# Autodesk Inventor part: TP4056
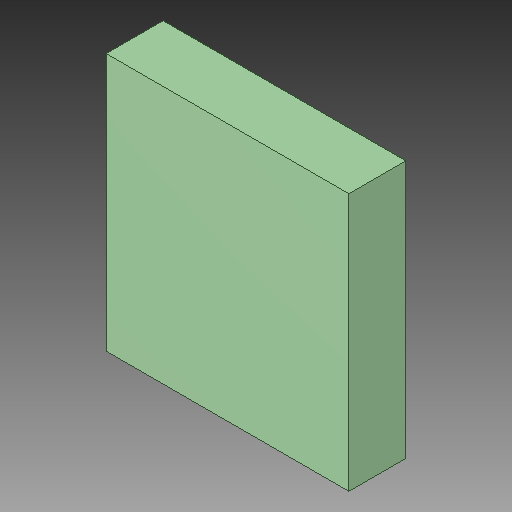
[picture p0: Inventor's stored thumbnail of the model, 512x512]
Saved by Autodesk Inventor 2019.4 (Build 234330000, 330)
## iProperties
Created: 2019-11
Part Number: TP4056
Material: Generic
Document SubType Name: Modeling
Designer: Willist
Density: 1 g/cm^3
Appearance: SOP-8, TP4056
Author: Willist
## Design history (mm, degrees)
sketch "SOP-8, TP4056_35"
  geometry: L1 (-2.163, 2.264)-(2.1, 2.264); L2 (2.1, 2.264)-(2.1, -2.264); L3 (2.1, -2.264)-(-2.163, -2.264); L4 (-2.163, -2.264)-(-2.163, 2.264)
  constraints: 8 end point
extrude "Extrusion1" join sketch "SOP-8, TP4056_35" distance "d0" = 1; taper "d1" = 0 deg
body "Solid1"
